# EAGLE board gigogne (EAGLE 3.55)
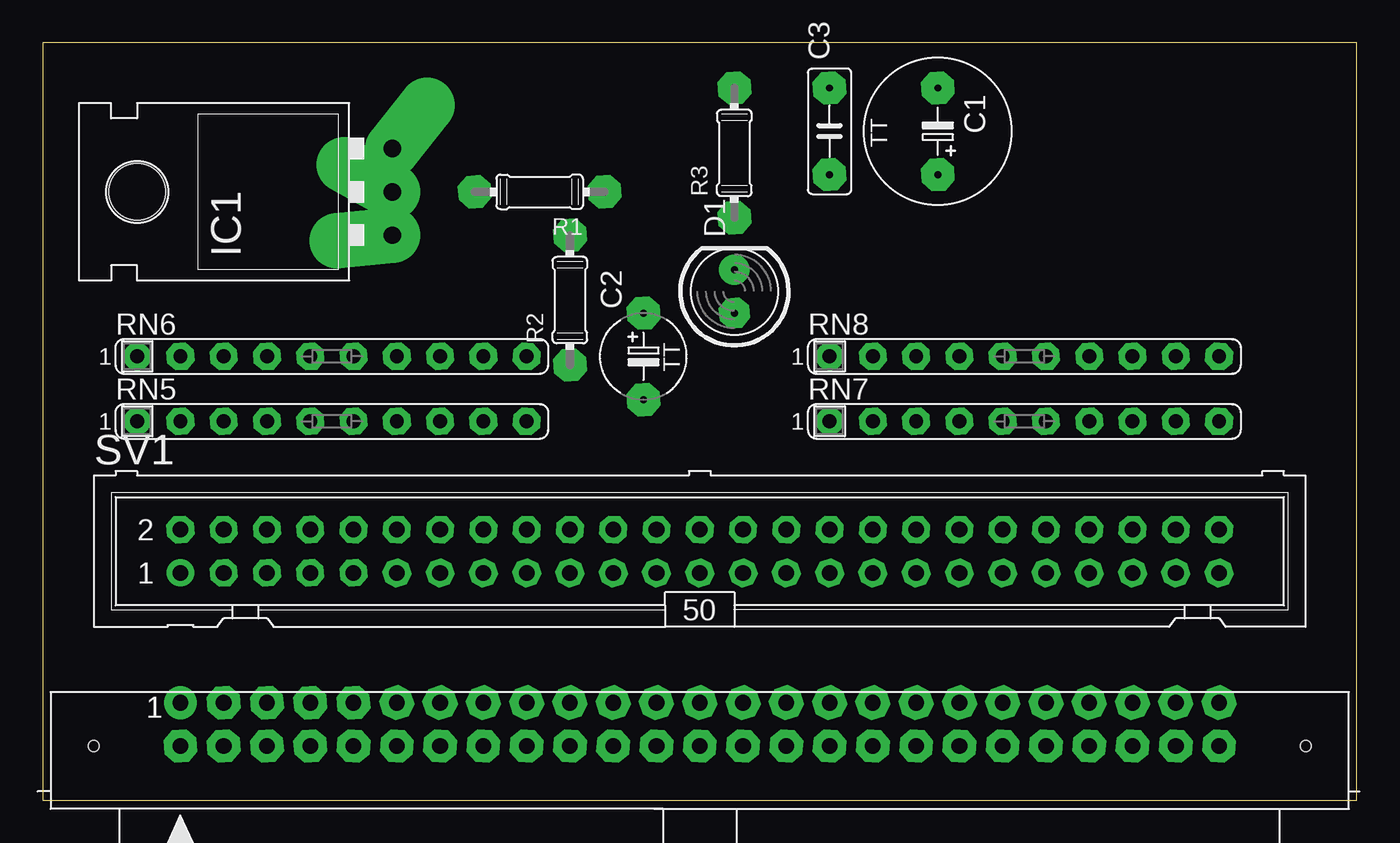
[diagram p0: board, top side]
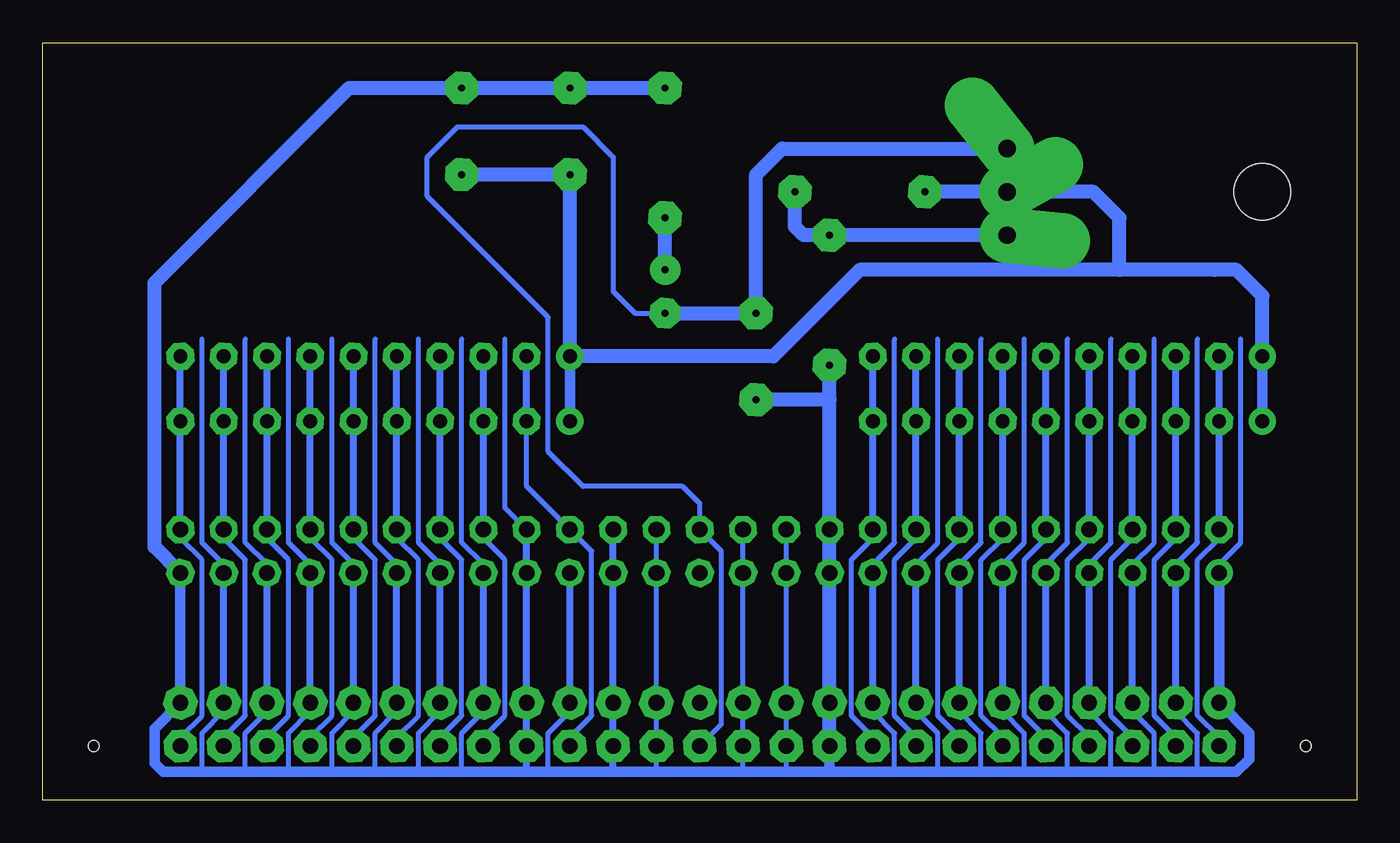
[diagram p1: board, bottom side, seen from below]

Size 77.14 x 44.44 mm. Coordinates in mm from the lower left corner, seen from the top.
Outline: 0,0 77.14,0 77.14,44.44 0,44.44 0,0
Copper layers used: Bottom

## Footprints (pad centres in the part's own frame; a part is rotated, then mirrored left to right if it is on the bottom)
P5-80 = drill 0.406 pad 1.93 octagon:  -2.54,0;  2.54,0
P5-50 = drill 0.406 pad 1.93 octagon:  -2.54,0;  2.54,0
B2,5 = drill 0.406 pad 1.93 octagon:  -2.54,0;  2.54,0
D5 = drill 0.406 pad 1.778 octagon:  -1.27,0 | drill 0.406 pad 1.778 round:  1.27,0
7TL = drill 1.016 pad 3.251 offset:  -2.54,-3.81;  0,-3.81;  2.54,-3.81 | hole 3.302: 0,11.176
04/7 = drill 0.406 pad 1.93 octagon:  -3.81,0;  3.81,0
L10 = drill 0.813 pad 1.6 round:  -11.43,0 | drill 0.813 pad 1.6 octagon:  -8.89,0;  -6.35,0;  -3.81,0;  -1.27,0;  1.27,0;  3.81,0;  6.35,0;  8.89,0;  11.43,0
50 = drill 0.914 pad 1.6 round:  -30.48,-1.27 | drill 0.914 pad 1.6 octagon:  -30.48,1.27;  -27.94,-1.27;  -27.94,1.27;  -25.4,-1.27;  -25.4,1.27;  -22.86,-1.27;  -22.86,1.27;  -20.32,-1.27;  -20.32,1.27;  -17.78,-1.27;  -17.78,1.27;  -15.24,-1.27;  -15.24,1.27;  -12.7,-1.27;  -12.7,1.27;  -10.16,-1.27;  -10.16,1.27;  -7.62,-1.27;  -7.62,1.27;  -5.08,-1.27;  -5.08,1.27;  -2.54,-1.27;  -2.54,1.27;  0,-1.27;  0,1.27;  2.54,-1.27;  2.54,1.27;  5.08,1.27;  5.08,-1.27;  7.62,-1.27;  7.62,1.27;  10.16,1.27;  10.16,-1.27;  12.7,-1.27;  12.7,1.27;  15.24,1.27;  15.24,-1.27;  17.78,-1.27;  17.78,1.27;  20.32,-1.27;  20.32,1.27;  22.86,-1.27;  22.86,1.27;  25.4,-1.27;  25.4,1.27;  27.94,-1.27;  27.94,1.27;  30.48,-1.27;  30.48,1.27
1050FC = drill 0.914 pad 1.93 octagon:  -30.48,-1.27;  -27.94,-1.27;  -27.94,1.27;  -25.4,-1.27;  -25.4,1.27;  -22.86,-1.27;  -22.86,1.27;  -20.32,-1.27;  -20.32,1.27;  -17.78,-1.27;  -17.78,1.27;  -15.24,-1.27;  -15.24,1.27;  -12.7,-1.27;  -12.7,1.27;  -10.16,-1.27;  -10.16,1.27;  -7.62,-1.27;  -7.62,1.27;  -5.08,-1.27;  -5.08,1.27;  -2.54,-1.27;  -2.54,1.27;  0,-1.27;  0,1.27;  2.54,1.27;  2.54,-1.27;  5.08,1.27;  5.08,-1.27;  7.62,1.27;  7.62,-1.27;  10.16,-1.27;  10.16,1.27;  12.7,-1.27;  12.7,1.27;  15.24,1.27;  15.24,-1.27;  17.78,-1.27;  17.78,1.27;  20.32,-1.27;  20.32,1.27;  22.86,-1.27;  22.86,1.27;  25.4,-1.27;  25.4,1.27;  27.94,-1.27;  27.94,1.27;  30.48,-1.27;  30.48,1.27 | drill 0.914 pad 1.93 round:  -30.48,1.27 | hole 0.61: -35.56,-1.27; 35.56,-1.27

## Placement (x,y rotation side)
C1  22æF  [P5-80]  52.54,39.24 270 top
C2  4.7æF  [P5-50]  35.27,26.03 90 top
C3  100nF  [B2,5]  46.19,39.24 90 top
D1  LED 5mm  [D5]  40.6,29.84 90 top
IC1  LM317T  [7TL]  16.73,35.68 90 top
R1  121  [04/7]  29.17,35.68 180 top
R2  154  [04/7]  30.95,29.33 90 top
R3  1k5  [04/7]  40.6,37.97 90 top
RN5  220  [L10]  16.98,22.22 0 top
RN6  220  [L10]  16.98,26.03 0 top
RN7  220  [L10]  57.62,22.22 0 top
RN8  220  [L10]  57.62,26.03 0 top
SV1  HE10-50M  [50]  38.57,14.6 0 top
SV2  ML50L  [1050FC]  38.57,4.44 0 top

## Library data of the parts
C1 C2 = CAP-TANT
C3 = CAP
D1 = LED
IC1 = V-REG
R1-R3 = R
RN5-RN8 = R-SIL
SV1 SV2 = CON-ML

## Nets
C2: RN5. RN6. SV1. SV2.
C4: RN5. RN6. SV1. SV2.
C6: RN5. RN6. SV1. SV2.
C8: RN5. RN6. SV1. SV2.
C10: RN5. RN6. SV1. SV2.
C12: RN5. RN6. SV1. SV2.
C14: RN5. RN6. SV1. SV2.
C16: RN5. RN6. SV1. SV2.
C18: RN5. RN6. SV1. SV2.
C26: C2. D1. IC1. SV1. SV2.
C32: RN7. RN8. SV1. SV2.
C36: RN7. RN8. SV1. SV2.
C38: RN7. RN8. SV1. SV2.
C40: RN7. RN8. SV1. SV2.
C42: RN7. RN8. SV1. SV2.
C44: RN7. RN8. SV1. SV2.
C46: RN7. RN8. SV1. SV2.
C48: RN7. RN8. SV1. SV2.
C50: RN7. RN8. SV1. SV2.
GND: C1. C2. C3. R2. R3. SV1. SV2.
N$1: C1. C3. IC1. R1. RN5. RN6. RN7. RN8.
N$2: IC1. R1. R2.
N$4: D1. R3.

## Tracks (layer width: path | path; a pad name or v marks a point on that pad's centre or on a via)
C2
  Bottom 0.305: 8.09,3.68 9.36,4.95 9.36,14.09 8.09,15.36 8.09,15.87
  Bottom 0.406: 8.09,15.87 8.09,22.22 8.09,26.03 | 8.09,3.17 8.09,3.68
C4
  Bottom 0.305: 10.63,3.68 11.9,4.95 11.9,14.09 10.63,15.36 10.63,15.87
  Bottom 0.406: 10.63,26.03 10.63,22.22 10.63,15.87 | 10.63,3.17 10.63,3.68
C6
  Bottom 0.305: 13.17,3.68 14.44,4.95 14.44,14.09 13.17,15.36 13.17,15.87
  Bottom 0.406: 13.17,15.87 13.17,22.22 13.17,26.03 | 13.17,3.17 13.17,3.68
C8
  Bottom 0.305: 15.71,3.68 16.98,4.95 16.98,14.09 15.71,15.36 15.71,15.87
  Bottom 0.406: 15.71,26.03 15.71,22.22 15.71,15.87 | 15.71,3.17 15.71,3.68
C10
  Bottom 0.305: 18.25,3.68 19.52,4.95 19.52,14.09 18.25,15.36 18.25,15.87
  Bottom 0.406: 18.25,15.87 18.25,22.22 18.25,26.03 | 18.25,3.17 18.25,3.68
C12
  Bottom 0.305: 20.79,3.68 22.06,4.95 22.06,14.09 20.79,15.36 20.79,15.87
  Bottom 0.406: 20.79,26.03 20.79,22.22 20.79,15.87 | 20.79,3.17 20.79,3.68
C14
  Bottom 0.305: 23.33,3.68 24.6,4.95 24.6,14.09 23.33,15.36 23.33,15.87
  Bottom 0.406: 23.33,15.87 23.33,22.22 23.33,26.03 | 23.33,3.17 23.33,3.68
C16
  Bottom 0.305: 25.87,3.68 27.14,4.95 27.14,14.09 25.87,15.36 25.87,15.87
  Bottom 0.406: 25.87,26.03 25.87,22.22 25.87,15.87 | 25.87,3.17 25.87,3.68
C18
  Bottom 0.305: 28.41,3.68 29.68,4.95 29.68,14.09 28.41,15.36 28.41,15.87
  Bottom 0.406: 28.41,15.87 RN5. RN6. | 28.41,3.17 28.41,3.68
C26
  Bottom 0.305: 38.57,3.17 37.3,4.44 37.3,14.6 38.57,15.87 38.57,17.39 39.59,18.41 45.43,18.41 47.46,20.44 47.46,28.32 54.57,35.43 54.57,37.71 52.79,39.49 45.43,39.49 43.65,37.71 43.65,37.46 43.65,29.84 42.38,28.57 40.6,28.57
  Bottom 0.61: 22.57,38.22 22.82,38.22
  Bottom 0.813: 40.6,28.57 C2. 35.27,36.7 33.74,38.22 22.57,38.22 IC1.
C32
  Bottom 0.305: 46.19,3.68 44.92,4.95 44.92,14.6 46.19,15.87 48.73,18.41 48.73,22.22
  Bottom 0.406: 48.73,22.22 48.73,26.03 | 46.19,3.17 46.19,3.68
C36
  Bottom 0.305: 51.27,3.68 50,4.95 50,14.09 51.27,15.36 51.27,15.87
  Bottom 0.406: 51.27,15.87 51.27,22.22 51.27,26.03 | 51.27,3.17 51.27,3.68
C38
  Bottom 0.305: 53.81,3.68 52.54,4.95 52.54,14.09 53.81,15.36 53.81,15.87
  Bottom 0.406: 53.81,26.03 53.81,22.22 53.81,15.87 | 53.81,3.17 53.81,3.68
C40
  Bottom 0.305: 56.35,3.68 55.08,4.95 55.08,14.09 56.35,15.36 56.35,15.87
  Bottom 0.406: 56.35,15.87 56.35,22.22 56.35,26.03 | 56.35,3.17 56.35,3.68
C42
  Bottom 0.305: 58.89,3.68 57.62,4.95 57.62,14.09 58.89,15.36 58.89,15.87
  Bottom 0.406: 58.89,26.03 58.89,22.22 58.89,15.87 | 58.89,3.17 58.89,3.68
C44
  Bottom 0.305: 61.43,3.68 60.16,4.95 60.16,14.09 61.43,15.36 61.43,15.87
  Bottom 0.406: 61.43,15.87 61.43,22.22 61.43,26.03 | 61.43,3.17 61.43,3.68
C46
  Bottom 0.305: 63.97,3.68 62.7,4.95 62.7,14.09 63.97,15.36 63.97,15.87
  Bottom 0.406: 63.97,26.03 63.97,22.22 63.97,15.87 | 63.97,3.17 63.97,3.68
C48
  Bottom 0.305: 66.51,3.68 65.24,4.95 65.24,14.09 66.51,15.36 66.51,15.87
  Bottom 0.406: 66.51,15.87 66.51,22.22 66.51,26.03 | 66.51,3.17 66.51,3.68
C50
  Bottom 0.305: 69.05,3.68 67.78,4.95 67.78,14.09 69.05,15.36 SV1.
  Bottom 0.406: RN8. RN7. SV1. | 69.05,3.17 69.05,3.68
GND
  Bottom 0.305: 10.63,5.2 9.36,3.93 9.36,1.65 | 13.17,5.2 11.9,3.93 11.9,1.65 | 15.71,5.2 14.44,3.93 14.44,1.65 | 18.25,5.2 16.98,3.93 16.98,1.65 | 20.79,5.2 19.52,3.93 19.52,1.65 | 23.33,5.2 22.06,3.93 22.06,1.65 | 25.87,5.2 24.6,3.93 24.6,1.65 | 28.41,5.2 27.14,3.93 27.14,1.65 | 66.51,5.2 67.78,3.93 67.78,1.65 | 63.97,5.2 65.24,3.93 65.24,1.65 | 61.43,5.2 62.7,3.93 62.7,1.65 | 58.89,5.2 60.16,3.93 60.16,1.65 | 56.35,5.2 57.62,3.93 57.62,1.65 | 53.81,5.2 55.08,3.93 55.08,1.65 | 51.27,5.2 52.54,3.93 52.54,1.65 | 46.19,5.2 47.46,3.93 47.46,1.65 | 8.09,13.33 8.09,13.84 6.82,15.11 6.82,27.05 | 10.63,13.33 10.63,13.84 9.36,15.11 9.36,27.05 | 13.17,13.33 13.17,13.84 11.9,15.11 11.9,27.05 | 15.71,13.33 15.71,13.84 14.44,15.11 14.44,27.05 | 18.25,13.33 18.25,13.84 16.98,15.11 16.98,27.05 | 20.79,13.33 20.79,13.84 19.52,15.11 19.52,27.05 | 23.33,13.33 23.33,13.84 22.06,15.11 22.06,27.05 | 25.87,13.33 25.87,13.84 24.6,15.11 24.6,27.05 | 28.41,13.33 28.41,13.84 27.14,15.11 27.14,27.05 | 51.27,13.33 51.27,13.84 52.54,15.11 52.54,27.05 | 53.81,13.33 53.81,13.84 55.08,15.11 55.08,27.05 | 56.35,13.33 56.35,13.84 57.62,15.11 57.62,27.05 | 58.89,13.33 58.89,13.84 60.16,15.11 60.16,27.05 | 61.43,13.33 61.43,13.84 62.7,15.11 62.7,27.05 | 63.97,13.33 63.97,13.84 65.24,15.11 65.24,27.05 | 66.51,13.33 66.51,13.84 67.78,15.11 67.78,27.05 | 48.73,15.87 50,17.14 50,27.05 | 33.24,15.62 33.49,15.62 33.49,15.87 33.49,13.33 33.49,5.71 33.49,3.17 33.49,1.65 | 36.03,1.65 36.03,3.17 36.03,5.71 36.03,13.33 36.03,15.87 | 41.11,1.65 41.11,3.17 41.11,5.71 41.11,13.33 41.11,15.87
  Bottom 0.406: 10.63,13.33 10.63,5.71 10.63,5.2 | 13.17,13.33 13.17,5.71 13.17,5.2 | 15.71,13.33 15.71,5.71 15.71,5.2 | 18.25,13.33 18.25,5.71 18.25,5.2 | 43.65,15.87 43.65,13.33 43.65,5.71 43.65,3.17 43.65,1.65 | 23.33,13.33 23.33,5.71 23.33,5.2 | 25.87,13.33 25.87,5.71 25.87,5.2 | 28.41,13.33 28.41,5.71 28.41,5.2 | 46.19,13.33 46.19,5.71 46.19,5.2 | 48.73,15.87 48.73,13.33 48.73,5.71 48.73,3.17 48.73,1.65 | 51.27,13.33 51.27,5.71 51.27,5.2 | 53.81,13.33 53.81,5.71 53.81,5.2 | 56.35,13.33 56.35,5.71 56.35,5.2 | 58.89,13.33 58.89,5.71 58.89,5.2 | 61.43,13.33 61.43,5.71 61.43,5.2 | 63.97,13.33 63.97,5.71 63.97,5.2 | 66.51,13.33 66.51,5.71 66.51,5.2 | 20.79,5.2 20.79,5.71 20.79,13.33
  Bottom 0.61: 8.09,13.33 8.09,5.71 6.31,3.93 6.31,2.41 7.07,1.65 9.36,1.65 11.9,1.65 14.44,1.65 16.98,1.65 19.52,1.65 22.06,1.65 24.6,1.65 27.14,1.65 30.95,1.65 | 69.05,13.33 SV2. 70.57,4.19 70.57,2.15 70.07,1.65 67.78,1.65 65.24,1.65 62.7,1.65 60.16,1.65 57.62,1.65 55.08,1.65 52.54,1.65 48.73,1.65 47.46,1.65 43.65,1.65 41.11,1.65 36.03,1.65 33.49,1.65 30.95,1.65 | 30.95,1.65 30.95,3.17
  Bottom 0.813: 30.95,3.17 30.95,5.71 30.95,13.33 30.95,15.87 30.95,23.49 | 69.05,13.33 70.57,14.85 70.57,30.35 59.14,41.78 52.54,41.78 C3. R3. | 30.95,23.49 30.95,25.52 | 30.95,23.49 35.27,23.49
N$1
  Bottom 0.61: 5.55,22.22 5.55,26.03 | 46.19,26.03 46.19,22.22 | 8.34,31.11 10.88,31.11 | 30.44,29.84 29.43,30.86
  Bottom 0.813: R1. 20.54,35.68 15.46,35.68 13.93,34.16 13.93,31.11 | 5.55,26.03 5.55,29.59 7.07,31.11 8.34,31.11 13.93,31.11 | 13.93,31.11 29.17,31.11 30.44,29.84 34.25,26.03 46.19,26.03 46.19,36.7 C1.
N$2
  Bottom 0.813: 20.54,33.14 R2. 32.47,33.14 32.98,33.65 32.98,35.68
N$4
  Bottom 0.813: D1. 40.6,34.16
